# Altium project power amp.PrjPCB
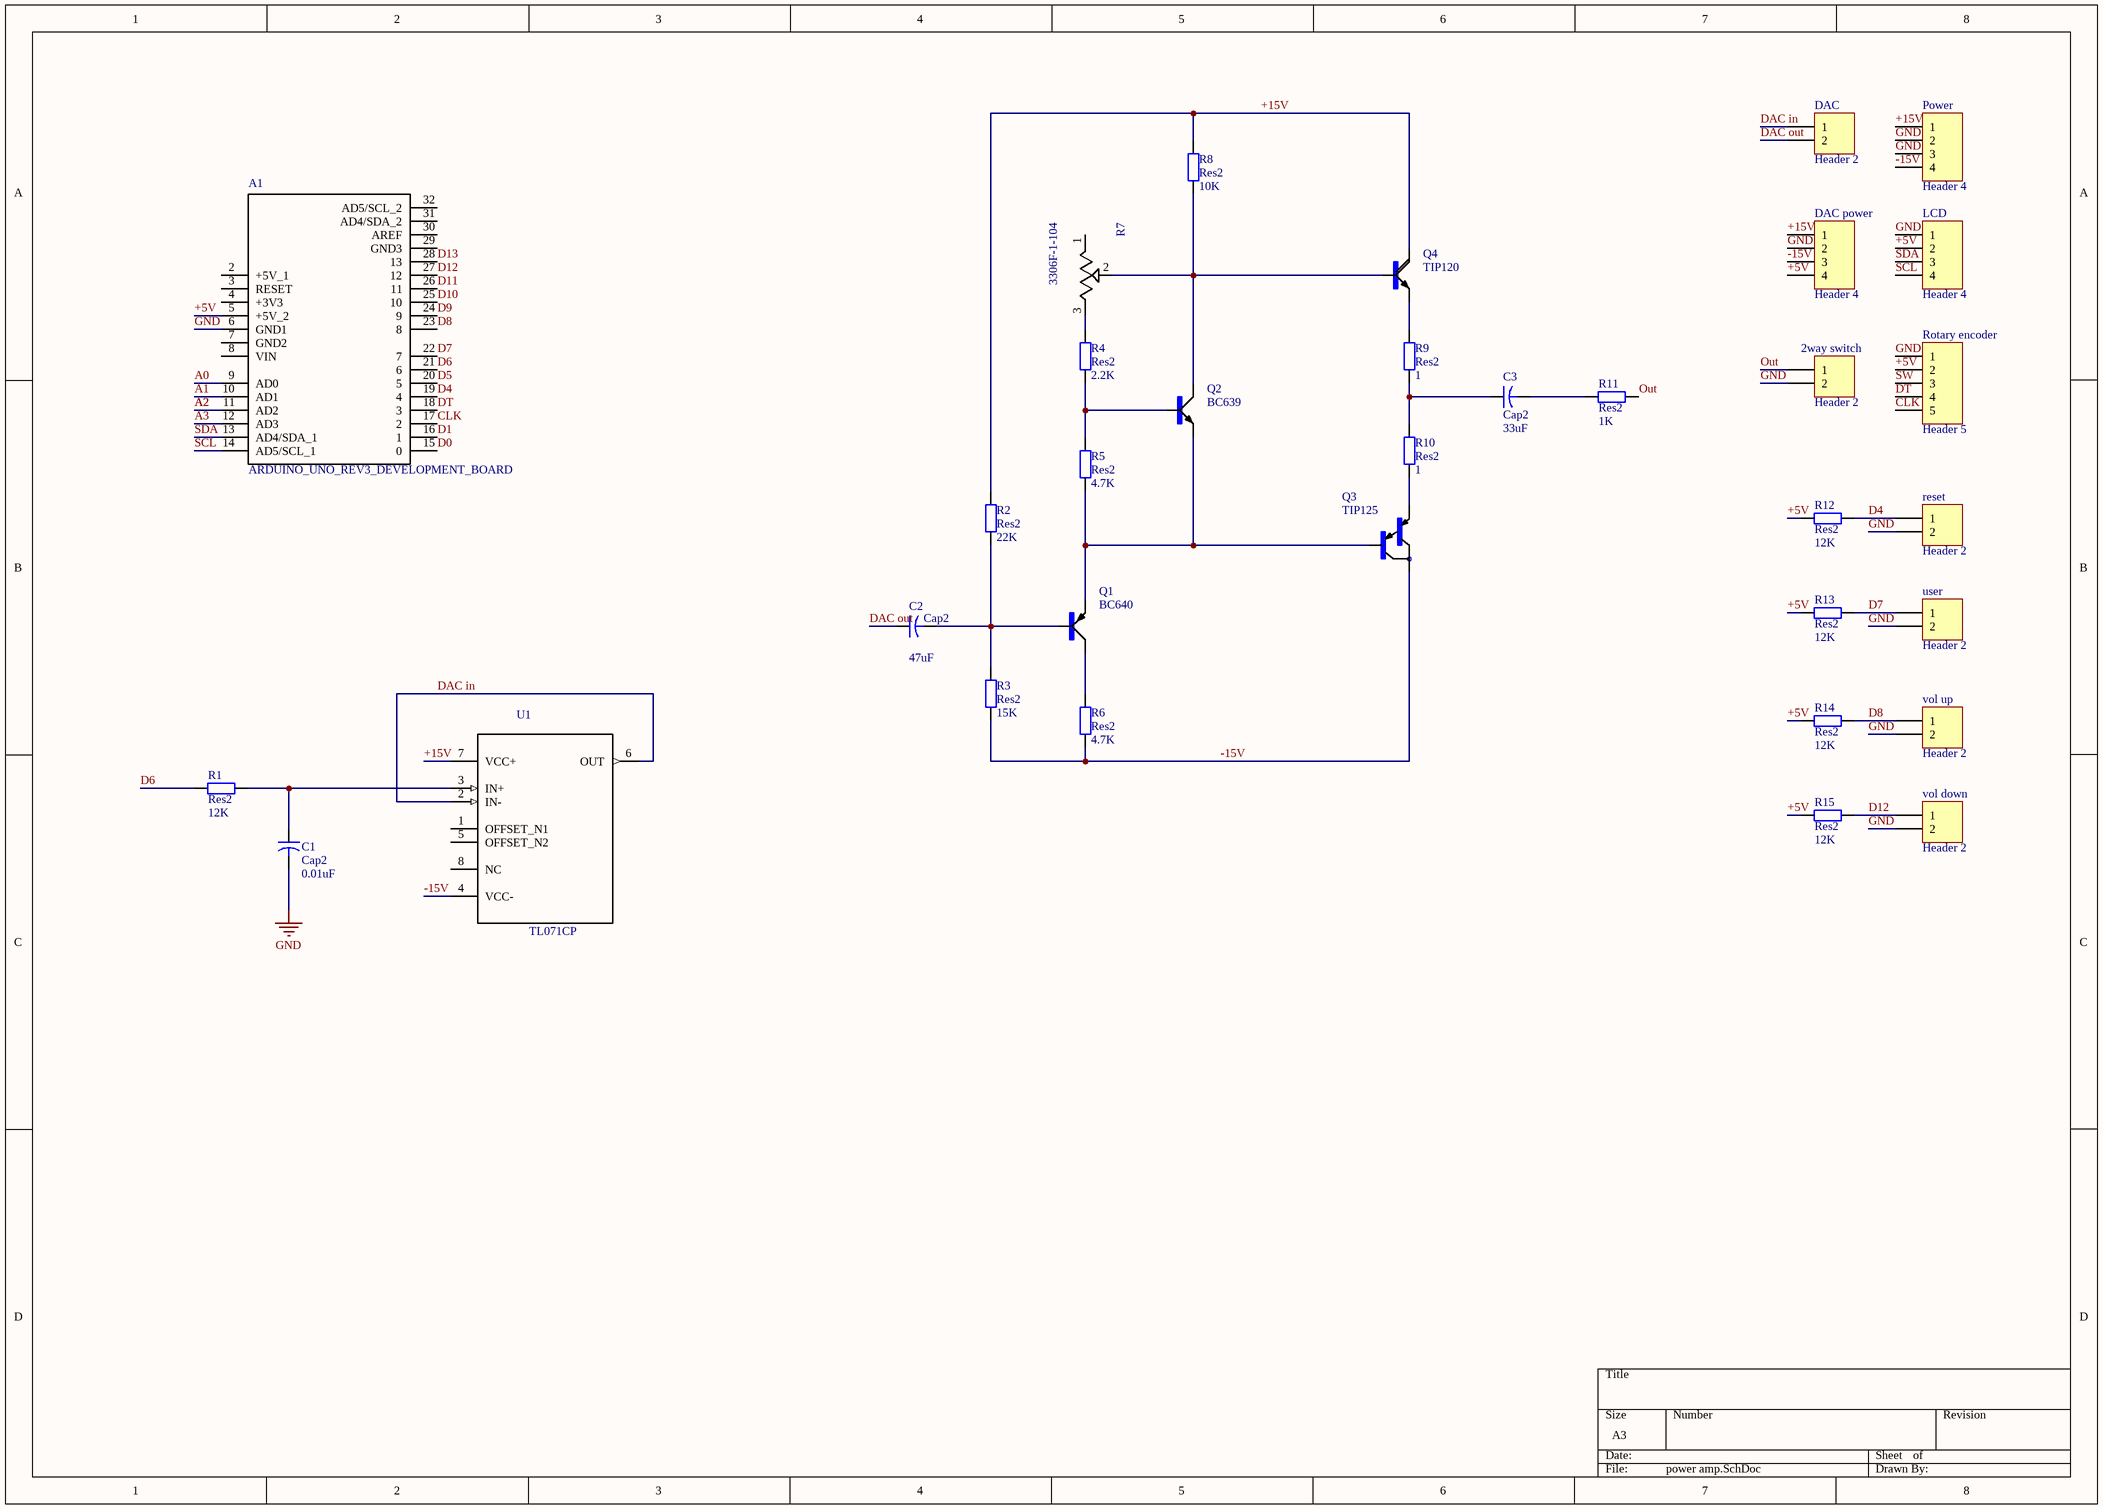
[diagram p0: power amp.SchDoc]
1 sheet, 34 parts. Net scope: global (net labels, ports and power ports of the same name join across sheets).
Board file: power amp.PcbDoc

## Sheet power amp.SchDoc
size A3

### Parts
2way_switch  Header 2  [HDR1X2]
A1  ARDUINO_UNO_REV3_DEVELOPMENT_BOARD  [*ARDUINO_UNO_REV3_DEVELOPMENT_BOARD]
C1  Cap2  value 0.01uF  [CAPR5-4X5]
C2  Cap2  value 47uF  [CAPR5-4X5]
C3  Cap2  value 33uF  [CAPR5-4X5]
DAC  Header 2  [HDR1X2]
DAC_power  Header 4  [HDR1X4]
LCD  Header 4  [HDR1X4]
Power  Header 4  [HDR1X4]
Q1  BC640  [*SOT54D_BC640(Primary)]
Q2  BC639  [*SOT54D_BC639(Primary)]
Q3  TIP125  [*TO220]
Q4  TIP120  [*TO220AH_TIP120(Primary)]
R1  Res2  value 12K  [AXIAL-0.4]
R2  Res2  value 22K  [AXIAL-0.4]
R3  Res2  value 15K  [AXIAL-0.4]
R4  Res2  value 2.2K  [AXIAL-0.4]
R5  Res2  value 4.7K  [AXIAL-0.4]
R6  Res2  value 4.7K  [AXIAL-0.4]
R7  3306F-1-104  [*TRIM_3306F-1-104]
R8  Res2  value 10K  [AXIAL-0.4]
R9  Res2  value 1  [AXIAL-0.4]
R10  Res2  value 1  [AXIAL-0.4]
R11  Res2  value 1K  [AXIAL-0.4]
R12  Res2  value 12K  [AXIAL-0.4]
R13  Res2  value 12K  [AXIAL-0.4]
R14  Res2  value 12K  [AXIAL-0.4]
R15  Res2  value 12K  [AXIAL-0.4]
reset  Header 2  [HDR1X2]
Rotary_encoder  Header 5  [HDR1X5]
U1  TL071CP  [*DIP254P762X508-8]
user  Header 2  [HDR1X2]
vol_down  Header 2  [HDR1X2]
vol_up  Header 2  [HDR1X2]

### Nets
GND: 2way_switch.2 A1.6(GND1) C1.2 DAC_power.2 LCD.1 Power.2 Power.3 reset.2 Rotary_encoder.1 user.2 vol_down.2 vol_up.2
+5V: A1.5(+5V_2) DAC_power.4 LCD.2 R12.1 R13.1 R14.1 R15.1 Rotary_encoder.2
+15V: DAC_power.1 Power.1 Q4.C R2.2 R8.2 U1.7(VCC+)
-15V: DAC_power.3 Power.4 Q3.2(C) R3.1 R6.1 U1.4(VCC-)
A0: A1.9(AD0)
A1: A1.10(AD1)
A2: A1.11(AD2)
A3: A1.12(AD3)
CLK: A1.17(2) Rotary_encoder.5
D0: A1.15(0)
D1: A1.16(1)
D4: A1.19(4) R12.2 reset.1
D5: A1.20(5)
D6: A1.21(6) R1.1
D7: A1.22(7) R13.2 user.1
D8: A1.23(8) R14.2 vol_up.1
D9: A1.24(9)
D10: A1.25(10)
D11: A1.26(11)
D12: A1.27(12) R15.2 vol_down.1
D13: A1.28(13)
DAC in: DAC.1 U1.2(IN-) U1.6(OUT)
DAC out: C2.1 DAC.2
DT: A1.18(3) Rotary_encoder.4
Out: 2way_switch.1 R11.1
SCL: A1.14(AD5/SCL_1) LCD.4
SDA: A1.13(AD4/SDA_1) LCD.3
SW: Rotary_encoder.3
NetC1_1: C1.1 R1.2 U1.3(IN+)
NetC2_2: C2.2 Q1.B R2.1 R3.2
NetC3_1: C3.1 R9.1 R10.2
NetC3_2: C3.2 R11.2
NetQ1_C: Q1.C R6.2
NetQ1_E: Q1.E Q2.E Q3.1(B) R5.1
NetQ2_B: Q2.B R4.1 R5.2
NetQ2_C: Q2.C Q4.B R7.2(W) R8.1
NetQ3_3: Q3.3(E) R10.1
NetQ4_E: Q4.E R9.2
NetR4_2: R4.2 R7.3(CW)

Not connected (* = marked no-connect by the designer): A1 2(+5V_1) 3(RESET) 4(+3V3) 7(GND2) 8(VIN) 29(GND3) 30(AREF) 31(AD4/SDA_2) 32(AD5/SCL_2); R7 1(CCW); U1 1(OFFSET_N1) 5(OFFSET_N2) 8(NC)

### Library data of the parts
2way_switch DAC reset user vol_down vol_up = Header 2: Header, 2-Pin
A1 = ARDUINO_UNO_REV3_DEVELOPMENT_BOARD: Plated Through Hole Protoboard Arduino Mega Platform Evaluation Expansion Board; MP: ARDUINO UNO REV3 DEVELOPMENT BOARD
C1-C3 = Cap2: Capacitor
DAC_power LCD Power = Header 4: Header, 4-Pin
Q1 = BC640: Bipolar _BJT_ Transistor PNP 80V 500mA 150MHz 625mW Through Hole TO-92-3; MF: ON Semiconductor
Q2 = BC639: Bipolar _BJT_ Transistor NPN 80V 1A 200MHz 625mW Through Hole TO-92-3; MF: ON Semiconductor
Q3 = TIP125: Bipolar _BJT_ Transistor PNP - Darlington 60V 5A 2W Through Hole TO-220-3; MF: ON Semiconductor
Q4 = TIP120: Bipolar _BJT_ Transistor NPN - Darlington 60V 5A 2W Through Hole TO-220-3; MF: ON Semiconductor
R1-R6 R8-R15 = Res2: Resistor
R7 = 3306F-1-104: 100 kOhms 0.2W, 1/5W PC Pins Through Hole Trimmer Potentiometer Cermet 1 Turn Top Adjustment; MF: Bourns
Rotary_encoder = Header 5: Header, 5-Pin
U1 = TL071CP: J-FET Amplifier 1 Circuit 8-PDIP; MF: Texas Instruments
